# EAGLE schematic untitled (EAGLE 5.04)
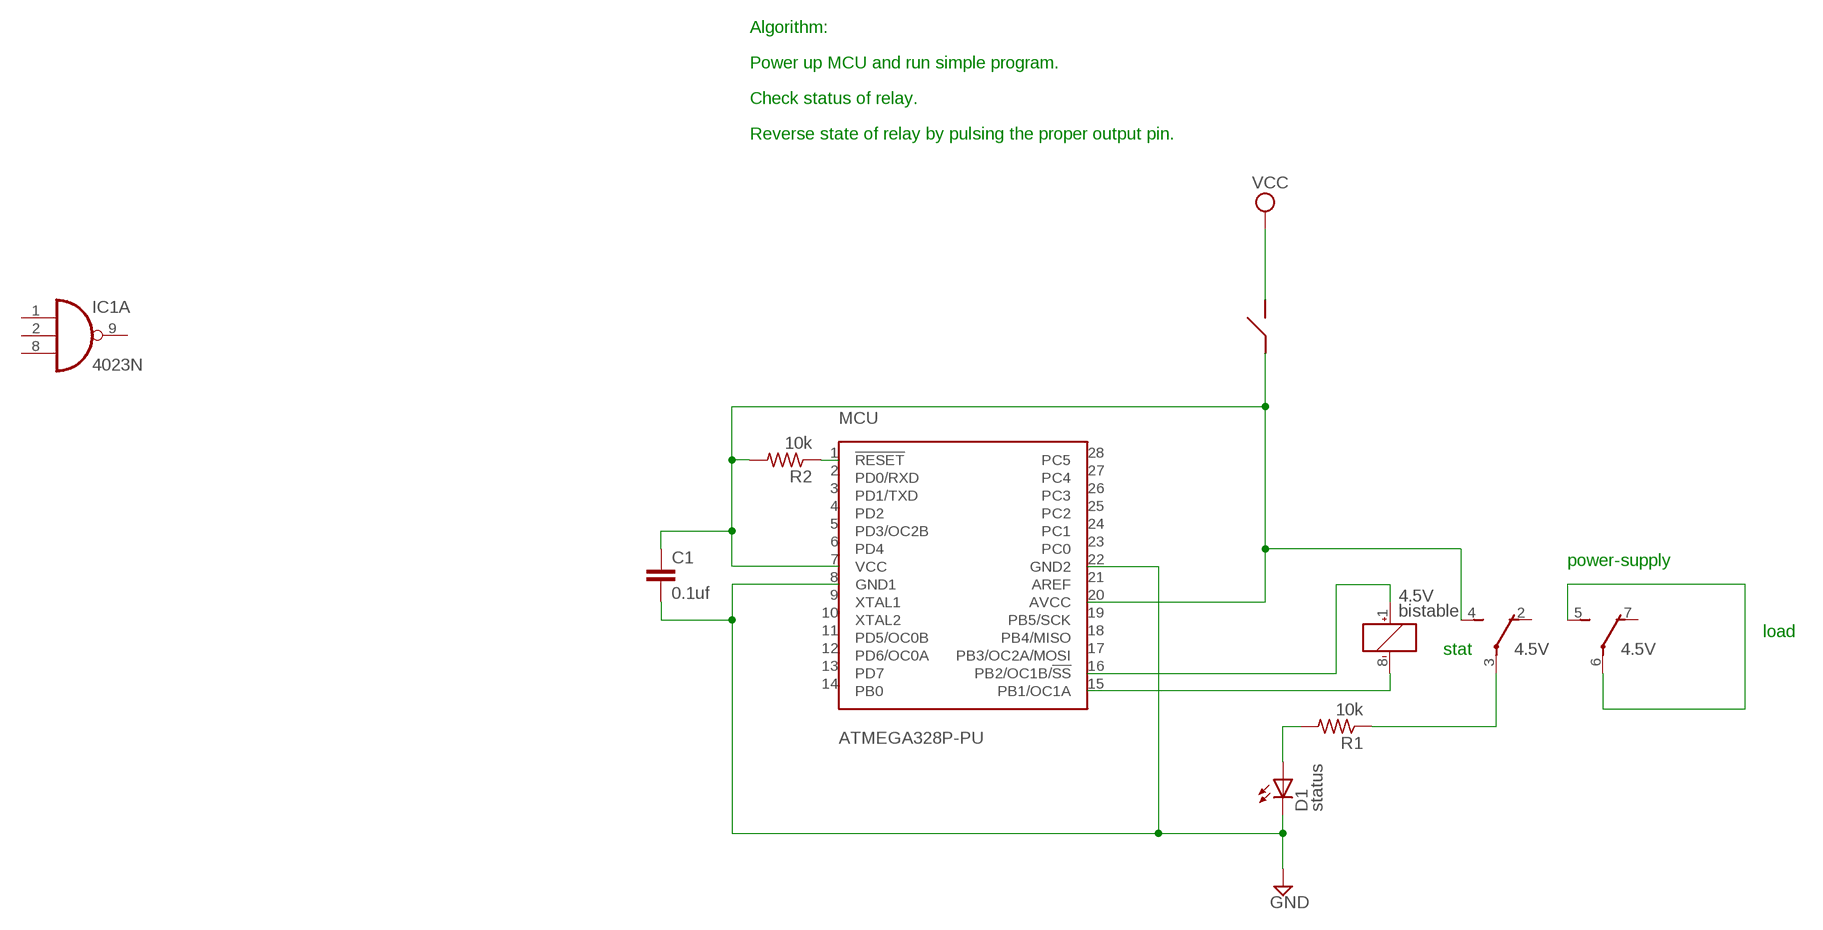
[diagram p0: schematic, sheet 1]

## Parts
4.5V  bistable  G6KU-2F-RF  [G6K-RF]
C1  0.1uf  C-EUC0603  [C0603]
D1  status  SFH482  [SFH482]
IC1  4023N  [DIL14]
MCU  ATMEGA328P-PU  [DIL28-3]
R1  10k  R-US_0309/12  [0309/12]
R2  10k  R-US_0309/12  [0309/12]
U$2  PUSH-BUTTON-SWITCH  [2SIL]

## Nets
GND: C1.2 D1.K(C) MCU.8(GND1) MCU.22(GND2)
N$1: D1.A R1.2
N$2: 4.5V.3(A:P) R1.1
N$3: 4.5V.4(A:S) C1.1 MCU.7(VCC) MCU.20(AVCC) R2.2 U$2.NO
N$4: MCU.1(!RESET) R2.1
N$5: 4.5V.8(1:-) MCU.15(PB1/OC1A)
N$6: 4.5V.1(1:+) MCU.16(PB2/OC1B/!SS)
N$7: 4.5V.5(B:S) 4.5V.6(B:P)
VCC: U$2.COM
Unconnected: 4.5V.2(A:O) 4.5V.7(B:O) 4.5V.A(S1:SH) 4.5V.B(S2:SH) IC1.1(A:I0) IC1.2(A:I1) IC1.3(B:I0) IC1.4(B:I1) IC1.5(B:I2) IC1.6(B:O) IC1.8(A:I2) IC1.9(A:O) IC1.10(C:O) IC1.11(C:I0) IC1.12(C:I1) IC1.13(C:I2) MCU.2(PD0/RXD) MCU.3(PD1/TXD) MCU.4(PD2) MCU.5(PD3/OC2B) MCU.6(PD4) MCU.9(XTAL1) MCU.10(XTAL2) MCU.11(PD5/OC0B) MCU.12(PD6/OC0A) MCU.13(PD7) MCU.14(PB0) MCU.17(PB3/OC2A/MOSI) MCU.18(PB4/MISO) MCU.19(PB5/SCK) MCU.21(AREF) MCU.23(PC0) MCU.24(PC1) MCU.25(PC2) MCU.26(PC3) MCU.27(PC4) MCU.28(PC5)

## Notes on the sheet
- Algorithm:
- Power up MCU and run simple program.
- Check status of relay.
- Reverse state of relay by pulsing the proper output pin.
- power-supply
- load
- stat

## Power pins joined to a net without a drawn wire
VDD: IC1.14(P:VDD)
VSS: IC1.7(P:VSS)

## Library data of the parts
4.5V = relay:G6K*-2F-RF: OMRON High Frequency Relay G6K-RF Compact High Frequency Relays with 2 Form C (DPDT) Contacts Handles 1 A, 30 VDC discrete load and 1 W at 1 GHz high frequency load D20G6KRF0602.pdf
C1 = resistor:C-EU: CAPACITOR, European symbol
D1 = led:SFH482: IR LED
IC1 = 40xx:4023: Triple 3-input NAND
MCU = trl:ATMEGA328P-PU
R1 R2 = rcl:R-US_: RESISTOR, American symbol
U$2 = trl:PUSH-BUTTON-SWITCH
